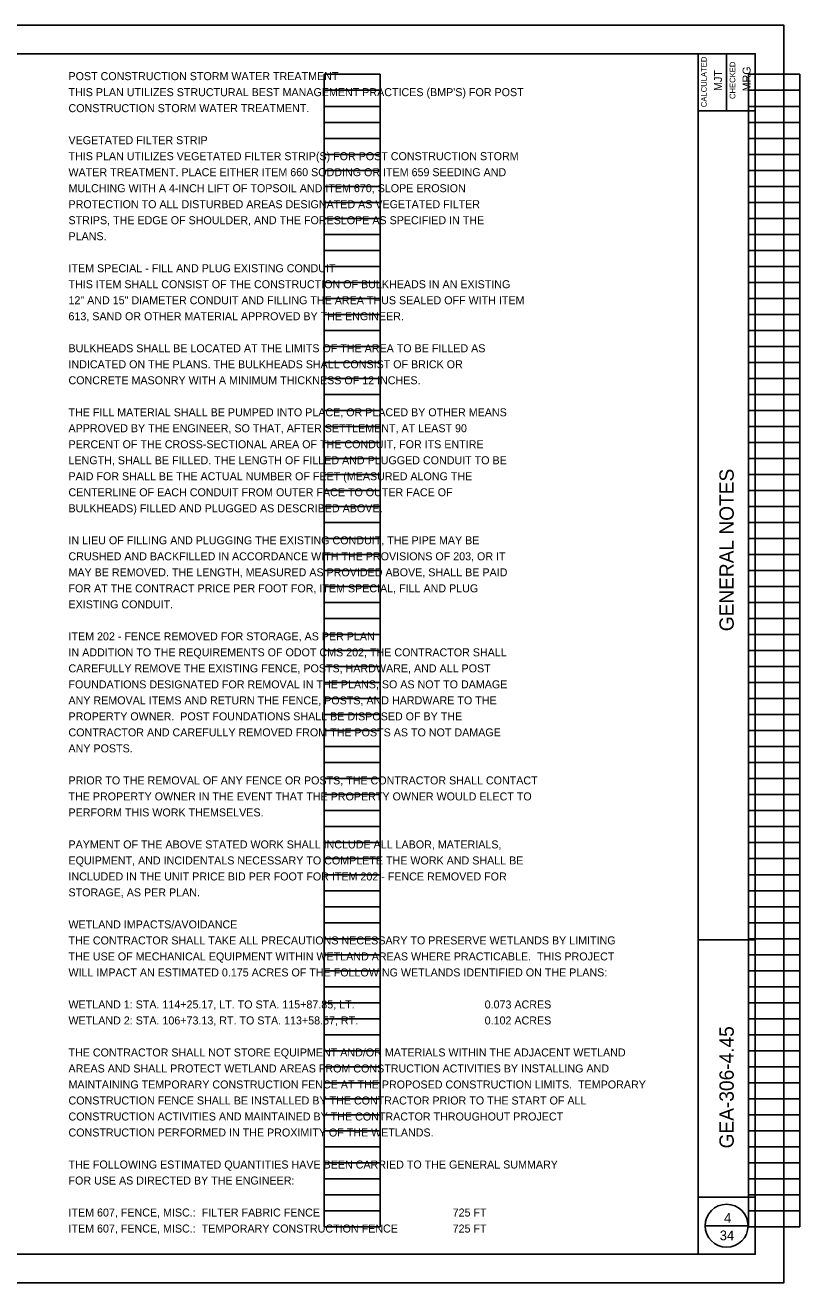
# Model space of a CAD drawing. Extents: x -16 to 102, y -13 to 9.
# Drawn here: x 48.59 to 62.14, y -12.91 to 9.09 of the extents above; entities that cross this region are included whole.
import ezdxf

# ---------------------------------------------------------------- set-up
doc = ezdxf.new("R2010")
doc.units = 0
for name, color, linetype in [('SH_Border', 7, 'Continuous'), ('SH_Cut_Line', 7, 'Continuous'), ('SH_Data', 7, 'Continuous'), ('SH_Text', 7, 'Continuous'), ('TX_P_1', 7, 'Continuous')]:
    doc.layers.add(name, color=color, linetype=linetype)

msp = doc.modelspace()

# ---------------------------------------------------------------- linework, layer by layer
at = {"layer": 'SH_Border'}
for p, q in [((60.361, -12.407), (60.361, 8.593)), ((60.861, 8.593), (60.861, 7.593)), ((60.361, 7.593), (61.361, 7.593)), ((60.361, -6.907), (61.361, -6.907)), ((60.361, -11.407), (61.361, -11.407))]:
    msp.add_line(p, q, dxfattribs=at)
msp.add_lwpolyline([(29.861, 8.593), (61.361, 8.593), (61.361, -12.407), (29.861, -12.407)], close=True, dxfattribs=at)
at = {"layer": 'SH_Cut_Line'}
msp.add_lwpolyline([(27.861, -12.907), (61.861, -12.907), (61.861, 9.093), (27.861, 9.093)], close=True, dxfattribs=at)
at = {"layer": 'SH_Data'}
for p, q in [((53.822, -11.927), (53.822, 8.233)), ((53.822, 8.233), (54.802, 8.233)), ((54.802, -11.927), (54.802, 8.233)), ((61.242, -11.927), (61.242, 8.233)), ((61.242, 8.233), (62.142, 8.233)), ((62.142, -11.927), (62.142, 8.233)), ((53.822, 7.953), (54.802, 7.953)), ((61.242, 7.953), (62.142, 7.953)), ((53.822, 7.673), (54.802, 7.673)), ((61.242, 7.673), (62.142, 7.673)), ((53.822, 7.393), (54.802, 7.393)), ((61.242, 7.393), (62.142, 7.393)), ((53.822, 7.113), (54.802, 7.113)), ((61.242, 7.113), (62.142, 7.113)), ((53.822, 6.833), (54.802, 6.833)), ((61.242, 6.833), (62.142, 6.833)), ((53.822, 6.553), (54.802, 6.553)), ((61.242, 6.553), (62.142, 6.553)), ((53.822, 6.273), (54.802, 6.273)), ((61.242, 6.273), (62.142, 6.273)), ((53.822, 5.993), (54.802, 5.993)), ((61.242, 5.993), (62.142, 5.993)), ((53.822, 5.713), (54.802, 5.713)), ((61.242, 5.713), (62.142, 5.713)), ((53.822, 5.433), (54.802, 5.433)), ((61.242, 5.433), (62.142, 5.433)), ((53.822, 5.153), (54.802, 5.153)), ((61.242, 5.153), (62.142, 5.153)), ((53.822, 4.873), (54.802, 4.873)), ((61.242, 4.873), (62.142, 4.873)), ((53.822, 4.593), (54.802, 4.593)), ((61.242, 4.593), (62.142, 4.593)), ((53.822, 4.313), (54.802, 4.313)), ((61.242, 4.313), (62.142, 4.313)), ((53.822, 4.033), (54.802, 4.033)), ((61.242, 4.033), (62.142, 4.033)), ((53.822, 3.753), (54.802, 3.753)), ((61.242, 3.753), (62.142, 3.753)), ((53.822, 3.473), (54.802, 3.473)), ((61.242, 3.473), (62.142, 3.473)), ((53.822, 3.193), (54.802, 3.193)), ((61.242, 3.193), (62.142, 3.193)), ((53.822, 2.913), (54.802, 2.913)), ((61.242, 2.913), (62.142, 2.913)), ((53.822, 2.633), (54.802, 2.633)), ((61.242, 2.633), (62.142, 2.633)), ((53.822, 2.353), (54.802, 2.353)), ((61.242, 2.353), (62.142, 2.353)), ((53.822, 2.073), (54.802, 2.073)), ((61.242, 2.073), (62.142, 2.073)), ((53.822, 1.793), (54.802, 1.793)), ((61.242, 1.793), (62.142, 1.793)), ((53.822, 1.513), (54.802, 1.513)), ((61.242, 1.513), (62.142, 1.513)), ((53.822, 1.233), (54.802, 1.233)), ((61.242, 1.233), (62.142, 1.233)), ((53.822, 0.953), (54.802, 0.953)), ((61.242, 0.953), (62.142, 0.953)), ((53.822, 0.673), (54.802, 0.673)), ((61.242, 0.673), (62.142, 0.673)), ((53.822, 0.393), (54.802, 0.393)), ((61.242, 0.393), (62.142, 0.393)), ((53.822, 0.113), (54.802, 0.113)), ((61.242, 0.113), (62.142, 0.113)), ((53.822, -0.167), (54.802, -0.167)), ((61.242, -0.167), (62.142, -0.167)), ((53.822, -0.447), (54.802, -0.447)), ((61.242, -0.447), (62.142, -0.447)), ((53.822, -0.727), (54.802, -0.727)), ((61.242, -0.727), (62.142, -0.727)), ((53.822, -1.007), (54.802, -1.007)), ((61.242, -1.007), (62.142, -1.007)), ((53.822, -1.287), (54.802, -1.287)), ((61.242, -1.287), (62.142, -1.287)), ((53.822, -1.567), (54.802, -1.567)), ((61.242, -1.567), (62.142, -1.567)), ((53.822, -1.847), (54.802, -1.847)), ((61.242, -1.847), (62.142, -1.847)), ((53.822, -2.127), (54.802, -2.127)), ((61.242, -2.127), (62.142, -2.127)), ((53.822, -2.407), (54.802, -2.407)), ((61.242, -2.407), (62.142, -2.407)), ((53.822, -2.687), (54.802, -2.687)), ((61.242, -2.687), (62.142, -2.687)), ((53.822, -2.967), (54.802, -2.967)), ((61.242, -2.967), (62.142, -2.967)), ((53.822, -3.247), (54.802, -3.247)), ((61.242, -3.247), (62.142, -3.247)), ((53.822, -3.527), (54.802, -3.527)), ((61.242, -3.527), (62.142, -3.527)), ((53.822, -3.807), (54.802, -3.807)), ((61.242, -3.807), (62.142, -3.807)), ((53.822, -4.087), (54.802, -4.087)), ((61.242, -4.087), (62.142, -4.087)), ((53.822, -4.367), (54.802, -4.367)), ((61.242, -4.367), (62.142, -4.367)), ((53.822, -4.647), (54.802, -4.647)), ((61.242, -4.647), (62.142, -4.647)), ((53.822, -4.927), (54.802, -4.927)), ((61.242, -4.927), (62.142, -4.927)), ((53.822, -5.207), (54.802, -5.207)), ((61.242, -5.207), (62.142, -5.207)), ((53.822, -5.487), (54.802, -5.487)), ((61.242, -5.487), (62.142, -5.487)), ((53.822, -5.767), (54.802, -5.767)), ((61.242, -5.767), (62.142, -5.767)), ((53.822, -6.047), (54.802, -6.047)), ((61.242, -6.047), (62.142, -6.047)), ((53.822, -6.327), (54.802, -6.327)), ((61.242, -6.327), (62.142, -6.327)), ((53.822, -6.607), (54.802, -6.607)), ((61.242, -6.607), (62.142, -6.607)), ((53.822, -6.887), (54.802, -6.887)), ((61.242, -6.887), (62.142, -6.887)), ((53.822, -7.167), (54.802, -7.167)), ((61.242, -7.167), (62.142, -7.167)), ((53.822, -7.447), (54.802, -7.447)), ((61.242, -7.447), (62.142, -7.447)), ((53.822, -7.727), (54.802, -7.727)), ((61.242, -7.727), (62.142, -7.727)), ((53.822, -8.007), (54.802, -8.007)), ((61.242, -8.007), (62.142, -8.007)), ((53.822, -8.287), (54.802, -8.287)), ((61.242, -8.287), (62.142, -8.287)), ((53.822, -8.567), (54.802, -8.567)), ((61.242, -8.567), (62.142, -8.567)), ((53.822, -8.847), (54.802, -8.847)), ((61.242, -8.847), (62.142, -8.847)), ((53.822, -9.127), (54.802, -9.127)), ((61.242, -9.127), (62.142, -9.127)), ((53.822, -9.407), (54.802, -9.407)), ((61.242, -9.407), (62.142, -9.407)), ((53.822, -9.687), (54.802, -9.687)), ((61.242, -9.687), (62.142, -9.687)), ((53.822, -9.967), (54.802, -9.967)), ((61.242, -9.967), (62.142, -9.967)), ((53.822, -10.247), (54.802, -10.247)), ((61.242, -10.247), (62.142, -10.247)), ((53.822, -10.527), (54.802, -10.527)), ((61.242, -10.527), (62.142, -10.527)), ((53.822, -10.807), (54.802, -10.807)), ((61.242, -10.807), (62.142, -10.807)), ((53.822, -11.087), (54.802, -11.087)), ((61.242, -11.087), (62.142, -11.087)), ((53.822, -11.367), (54.802, -11.367)), ((61.242, -11.367), (62.142, -11.367)), ((53.822, -11.647), (54.802, -11.647)), ((61.242, -11.647), (62.142, -11.647)), ((53.822, -11.927), (54.802, -11.927)), ((60.486, -11.907), (61.236, -11.907)), ((61.242, -11.927), (62.142, -11.927))]:
    msp.add_line(p, q, dxfattribs=at)
msp.add_circle((60.861, -11.907), 0.375, dxfattribs=at)

# ---------------------------------------------------------------- texts
for s, height, p in [('CALCULATED', 0.1, (60.514, 7.658)), ('CHECKED', 0.1, (61.014, 7.801)), ('MJT', 0.14, (60.781, 7.942)), ('MRG', 0.14, (61.281, 7.935)), ('GENERAL NOTES', 0.25, (60.986, -1.509)), ('GEA-306-4.45', 0.25, (60.986, -10.555))]:
    msp.add_text(s, height=height, rotation=90, dxfattribs=at).set_placement(p)
at = {"layer": 'SH_Text'}
for s, p in [('4', (60.816, -11.857)), ('34', (60.741, -12.162))]:
    msp.add_text(s, height=0.17, dxfattribs=at).set_placement(p)
at = {"layer": 'TX_P_1'}
for s, p in [('POST CONSTRUCTION STORM WATER TREATMENT', (49.349, 8.131)), ("THIS PLAN UTILIZES STRUCTURAL BEST MANAGEMENT PRACTICES (BMP'S) FOR POST", (49.349, 7.851)), ('CONSTRUCTION STORM WATER TREATMENT.', (49.349, 7.571)), ('VEGETATED FILTER STRIP', (49.349, 7.011)), ('THIS PLAN UTILIZES VEGETATED FILTER STRIP(S) FOR POST CONSTRUCTION STORM', (49.349, 6.731)), ('WATER TREATMENT. PLACE EITHER ITEM 660 SODDING OR ITEM 659 SEEDING AND', (49.349, 6.451)), ('MULCHING WITH A 4-INCH LIFT OF TOPSOIL AND ITEM 670, SLOPE EROSION', (49.349, 6.171)), ('PROTECTION TO ALL DISTURBED AREAS DESIGNATED AS VEGETATED FILTER', (49.349, 5.891)), ('STRIPS, THE EDGE OF SHOULDER, AND THE FORESLOPE AS SPECIFIED IN THE', (49.349, 5.611)), ('PLANS.', (49.349, 5.331)), ('ITEM SPECIAL - FILL AND PLUG EXISTING CONDUIT', (49.349, 4.771)), ('THIS ITEM SHALL CONSIST OF THE CONSTRUCTION OF BULKHEADS IN AN EXISTING', (49.349, 4.491)), ('12" AND 15" DIAMETER CONDUIT AND FILLING THE AREA THUS SEALED OFF WITH ITEM', (49.349, 4.211)), ('613, SAND OR OTHER MATERIAL APPROVED BY THE ENGINEER.', (49.349, 3.931)), ('BULKHEADS SHALL BE LOCATED AT THE LIMITS OF THE AREA TO BE FILLED AS', (49.349, 3.371)), ('INDICATED ON THE PLANS. THE BULKHEADS SHALL CONSIST OF BRICK OR', (49.349, 3.091)), ('CONCRETE MASONRY WITH A MINIMUM THICKNESS OF 12 INCHES.', (49.349, 2.811)), ('THE FILL MATERIAL SHALL BE PUMPED INTO PLACE, OR PLACED BY OTHER MEANS', (49.349, 2.251)), ('APPROVED BY THE ENGINEER, SO THAT, AFTER SETTLEMENT, AT LEAST 90', (49.349, 1.972)), ('PERCENT OF THE CROSS-SECTIONAL AREA OF THE CONDUIT, FOR ITS ENTIRE', (49.349, 1.692)), ('LENGTH, SHALL BE FILLED. THE LENGTH OF FILLED AND PLUGGED CONDUIT TO BE', (49.349, 1.412)), ('PAID FOR SHALL BE THE ACTUAL NUMBER OF FEET (MEASURED ALONG THE', (49.349, 1.132)), ('CENTERLINE OF EACH CONDUIT FROM OUTER FACE TO OUTER FACE OF', (49.349, 0.852)), ('BULKHEADS) FILLED AND PLUGGED AS DESCRIBED ABOVE.', (49.349, 0.572)), ('IN LIEU OF FILLING AND PLUGGING THE EXISTING CONDUIT, THE PIPE MAY BE', (49.349, 0.012)), ('CRUSHED AND BACKFILLED IN ACCORDANCE WITH THE PROVISIONS OF 203, OR IT', (49.349, -0.268)), ('MAY BE REMOVED. THE LENGTH, MEASURED AS PROVIDED ABOVE, SHALL BE PAID', (49.349, -0.548)), ('FOR AT THE CONTRACT PRICE PER FOOT FOR, ITEM SPECIAL, FILL AND PLUG', (49.349, -0.828)), ('EXISTING CONDUIT.', (49.349, -1.108)), ('ITEM 202 - FENCE REMOVED FOR STORAGE, AS PER PLAN', (49.349, -1.668)), ('IN ADDITION TO THE REQUIREMENTS OF ODOT CMS 202, THE CONTRACTOR SHALL', (49.349, -1.948)), ('CAREFULLY REMOVE THE EXISTING FENCE, POSTS, HARDWARE, AND ALL POST', (49.349, -2.228)), ('FOUNDATIONS DESIGNATED FOR REMOVAL IN THE PLANS, SO AS NOT TO DAMAGE', (49.349, -2.508)), ('ANY REMOVAL ITEMS AND RETURN THE FENCE, POSTS, AND HARDWARE TO THE', (49.349, -2.788)), ('PROPERTY OWNER.  POST FOUNDATIONS SHALL BE DISPOSED OF BY THE ', (49.349, -3.068)), ('CONTRACTOR AND CAREFULLY REMOVED FROM THE POSTS AS TO NOT DAMAGE', (49.349, -3.348)), ('ANY POSTS.', (49.349, -3.628)), ('PRIOR TO THE REMOVAL OF ANY FENCE OR POSTS, THE CONTRACTOR SHALL CONTACT', (49.349, -4.188)), ('THE PROPERTY OWNER IN THE EVENT THAT THE PROPERTY OWNER WOULD ELECT TO', (49.349, -4.468)), ('PERFORM THIS WORK THEMSELVES.', (49.349, -4.748)), ('PAYMENT OF THE ABOVE STATED WORK SHALL INCLUDE ALL LABOR, MATERIALS,', (49.349, -5.308)), ('EQUIPMENT, AND INCIDENTALS NECESSARY TO COMPLETE THE WORK AND SHALL BE', (49.349, -5.588)), ('INCLUDED IN THE UNIT PRICE BID PER FOOT FOR ITEM 202 - FENCE REMOVED FOR', (49.349, -5.868)), ('STORAGE, AS PER PLAN.', (49.349, -6.147)), ('WETLAND IMPACTS/AVOIDANCE', (49.349, -6.707)), ('THE CONTRACTOR SHALL TAKE ALL PRECAUTIONS NECESSARY TO PRESERVE WETLANDS BY LIMITING', (49.349, -6.987)), ('THE USE OF MECHANICAL EQUIPMENT WITHIN WETLAND AREAS WHERE PRACTICABLE.  THIS PROJECT', (49.349, -7.267)), ('WILL IMPACT AN ESTIMATED 0.175 ACRES OF THE FOLLOWING WETLANDS IDENTIFIED ON THE PLANS:', (49.349, -7.547)), ('WETLAND 1: STA. 114+25.17, LT. TO STA. 115+87.85, LT.', (49.349, -8.107)), ('0.073 ACRES', (56.629, -8.107)), ('WETLAND 2: STA. 106+73.13, RT. TO STA. 113+58.57, RT.', (49.349, -8.387)), ('0.102 ACRES', (56.629, -8.387)), ('THE CONTRACTOR SHALL NOT STORE EQUIPMENT AND/OR MATERIALS WITHIN THE ADJACENT WETLAND', (49.349, -8.947)), ('AREAS AND SHALL PROTECT WETLAND AREAS FROM CONSTRUCTION ACTIVITIES BY INSTALLING AND', (49.349, -9.227)), ('MAINTAINING TEMPORARY CONSTRUCTION FENCE AT THE PROPOSED CONSTRUCTION LIMITS.  TEMPORARY', (49.349, -9.507)), ('CONSTRUCTION FENCE SHALL BE INSTALLED BY THE CONTRACTOR PRIOR TO THE START OF ALL', (49.349, -9.787)), ('CONSTRUCTION ACTIVITIES AND MAINTAINED BY THE CONTRACTOR THROUGHOUT PROJECT', (49.349, -10.067)), ('CONSTRUCTION PERFORMED IN THE PROXIMITY OF THE WETLANDS.', (49.349, -10.347)), ('THE FOLLOWING ESTIMATED QUANTITIES HAVE BEEN CARRIED TO THE GENERAL SUMMARY', (49.349, -10.907)), ('FOR USE AS DIRECTED BY THE ENGINEER:', (49.349, -11.187)), ('ITEM 607, FENCE, MISC.:  FILTER FABRIC FENCE', (49.349, -11.747)), ('725 FT', (56.069, -11.747)), ('ITEM 607, FENCE, MISC.:  TEMPORARY CONSTRUCTION FENCE', (49.349, -12.027)), ('725 FT', (56.069, -12.027))]:
    msp.add_text(s, height=0.14, dxfattribs=at).set_placement(p)

doc.saveas('drawing.dxf')
